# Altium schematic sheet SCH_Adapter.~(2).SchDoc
size A
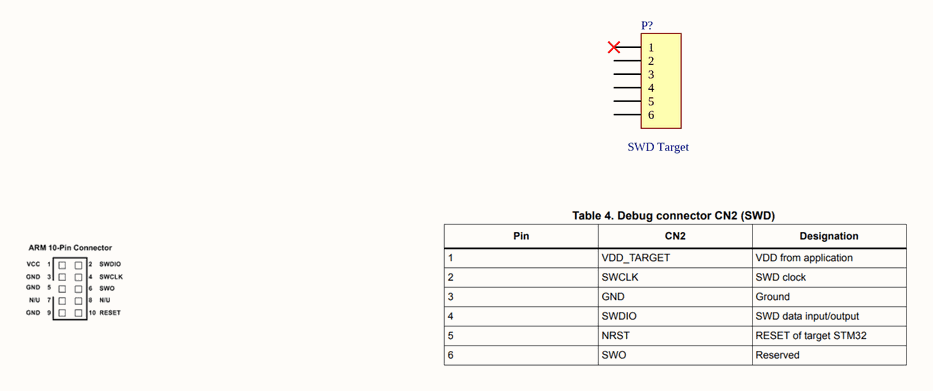
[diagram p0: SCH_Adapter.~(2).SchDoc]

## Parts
P?  SWD Target  [HDR1X6]

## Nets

Not connected (* = marked no-connect by the designer): P? 1* 2 3 4 5 6

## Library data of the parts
P? = Header 6: Header, 6-Pin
